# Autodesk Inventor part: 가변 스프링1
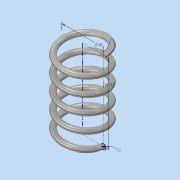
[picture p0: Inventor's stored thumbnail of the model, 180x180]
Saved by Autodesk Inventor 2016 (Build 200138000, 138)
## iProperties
Created: 2018-10
Part Number: 가변 스프링1
Material: 스테인레스 스틸
Document SubType Name: Modeling
Designer: 3sil_cad0123
Density: 8 g/cm^3
Appearance: 반연마
Mass: 6.22868 g
Surface Area: 15.8086 cm^2
Volume: 0.778585 cm^3
Author: 3sil_cad0123
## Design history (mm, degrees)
sketch "스케치1"
  geometry: L1 (0, 0)-(8, 0); L2 (8, 0)-(8, 24.5); L3 (8, 24.5)-(0, 24.5); L4 (0, 24.5)-(0, 0); C1 r 1 at (8, 0)
  constraints: 8 end point, 2 parallel, 1 centre point, 1 coincident, 1 horizontal, 1 perpendicular
  dimensions: "d0" = 16 diameter of L2 L4; "d1" = 2 diameter of C1; "d2" = 24.5 distance of L1.end L2.end (derived)
feature "코일1" pitch "d3" = 10; turns "d5" = 5; dims "d4" = 24.5 (= d2), "d6" = 0, angle "d7" = 90 deg, angle "d8" = 90 deg, "d9" = 0, "d10" = 0
sketch "스케치2"
  geometry: L1 (-7, 0)-(-9, 0) reference; 1 further point
  constraints: 1 horizontal alignment
extrude "돌출1" cut sketch "스케치2" stored distance "d11" = 10; taper "d12" = 0 deg
node "작업 평면2"
sketch "스케치3"
  geometry: L1 (-1, 0)-(1, 0) reference; 1 further point
  constraints: 1 horizontal alignment
extrude "돌출2" cut sketch "스케치3" stored distance "d14" = 10; taper "d15" = 0 deg
node "솔리드1"
node "절단 모서리 투영1"
node "절단 모서리 투영2"
other parameters: "d13" = 90 deg
